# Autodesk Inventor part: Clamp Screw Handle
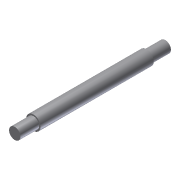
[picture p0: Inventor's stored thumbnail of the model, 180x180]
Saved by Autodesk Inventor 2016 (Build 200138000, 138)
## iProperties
Shininess: 77.0
Length Units: 11269
Angle Units: 11279
Time Units: 11290
Mass Units: 11283
Length Display Precision: 3
Angle Display Precision: 2
Compacted: True
Created: 2002-02
Part Number: Clamp Screw Handle
Document SubType Name: Modeling
Designer: ***
Density: 1 g/cm^3
Material: Generic
Mass: 7.51155 g
Surface Area: 32.9239 cm^2
Volume: 7.51155 cm^3
Appearance: Default
Density: 0.0
Volumn: 0.0
Area: 0.0
PropertySet Name: Model Information
Control State: 0
Master: False
Checked Out: False
Author: ***
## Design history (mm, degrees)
sketch "Sketch1"
  geometry: L1 (0, 105)-(4, 105); L2 (4, 105)-(4, 92); L3 (4, 92)-(5, 92); L4 (5, 92)-(5, 13); L5 (5, 13)-(4, 13); L6 (4, 13)-(4, 0); L7 (4, 0)-(0, 0); L8 (0, 0)-(0, 105)
  constraints: 16 end point, 5 parallel, 2 equal length, 1 collinear, 1 horizontal, 1 perpendicular
  dimensions: "d0" = 10 diameter of L4 L8; "d1" = 8 diameter of L2 L8; "d2" = 13 distance of L1.end L2.end; "d3" = 79 distance of L3.end L4.end
revolve "Revolution1" sketch "Sketch1" stored, may be unused: angle "d4" = 90 deg
body "Solid1"
